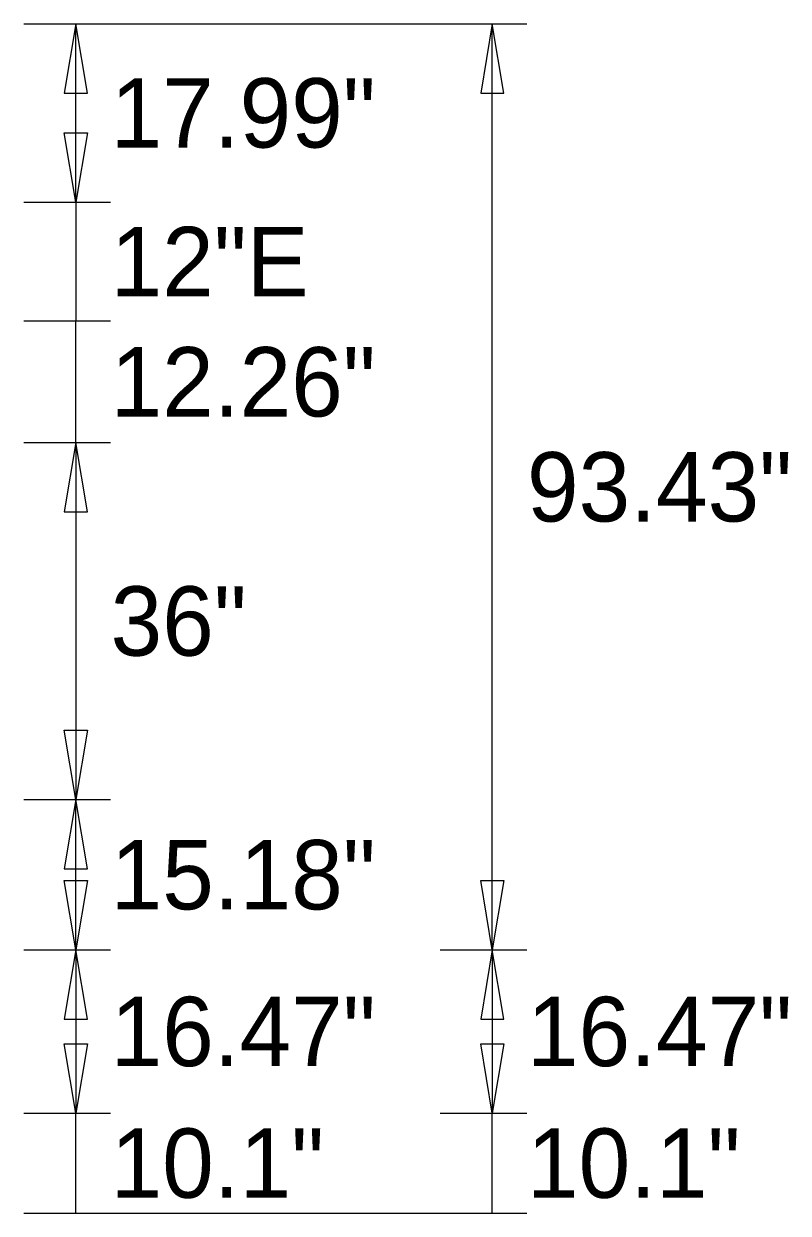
# Model space of a CAD drawing. Extents: x 2149934 to 2150188, y 145113 to 145238.
# Drawn here: x 2149967.33 to 2149973.75, y 145137.95 to 145147.95 of the extents above; entities that cross this region are included whole.
import ezdxf

# ---------------------------------------------------------------- set-up
doc = ezdxf.new("R2010")
doc.units = 0
doc.layers.add('GSDIMS', color=7, linetype='Continuous')

msp = doc.modelspace()

# ---------------------------------------------------------------- linework, layer by layer
at = {"layer": 'GSDIMS'}
for p, q in [((2149967.326, 145147.954), (2149968.055, 145147.954)), ((2149967.326, 145147.954), (2149970.826, 145147.954)), ((2149967.763, 145146.455), (2149967.763, 145147.954)), ((2149970.826, 145147.954), (2149971.555, 145147.954)), ((2149971.263, 145140.168), (2149971.263, 145147.954)), ((2149967.326, 145146.455), (2149968.055, 145146.455)), ((2149967.326, 145146.455), (2149968.055, 145146.455)), ((2149967.763, 145146.455), (2149967.763, 145145.455)), ((2149967.326, 145145.455), (2149968.055, 145145.455)), ((2149967.326, 145145.455), (2149968.055, 145145.455)), ((2149967.763, 145144.433), (2149967.763, 145145.455)), ((2149967.326, 145144.433), (2149968.055, 145144.433)), ((2149967.326, 145144.433), (2149968.055, 145144.433)), ((2149967.763, 145144.433), (2149967.763, 145141.433)), ((2149967.326, 145141.433), (2149968.055, 145141.433)), ((2149967.326, 145141.433), (2149968.055, 145141.433)), ((2149967.763, 145140.168), (2149967.763, 145141.433)), ((2149967.326, 145140.168), (2149968.055, 145140.168)), ((2149967.326, 145140.168), (2149968.055, 145140.168)), ((2149967.763, 145140.168), (2149967.763, 145138.795)), ((2149970.826, 145140.168), (2149971.555, 145140.168)), ((2149970.826, 145140.168), (2149971.555, 145140.168)), ((2149971.263, 145140.168), (2149971.263, 145138.795)), ((2149967.326, 145138.795), (2149968.055, 145138.795)), ((2149967.326, 145138.795), (2149968.055, 145138.795)), ((2149967.763, 145137.954), (2149967.763, 145138.795)), ((2149970.826, 145138.795), (2149971.555, 145138.795)), ((2149970.826, 145138.795), (2149971.555, 145138.795)), ((2149971.263, 145137.954), (2149971.263, 145138.795)), ((2149967.326, 145137.954), (2149968.055, 145137.954)), ((2149967.326, 145137.954), (2149970.826, 145137.954)), ((2149970.826, 145137.954), (2149971.555, 145137.954))]:
    msp.add_line(p, q, dxfattribs=at)
for points in [[(2149967.763, 145147.954), (2149967.666, 145147.37), (2149967.86, 145147.37)], [(2149971.263, 145147.954), (2149971.166, 145147.37), (2149971.36, 145147.37)], [(2149967.763, 145146.455), (2149967.666, 145147.038), (2149967.86, 145147.038)], [(2149967.763, 145144.433), (2149967.666, 145143.85), (2149967.86, 145143.85)], [(2149967.763, 145141.433), (2149967.666, 145142.016), (2149967.86, 145142.016)], [(2149967.763, 145141.433), (2149967.666, 145140.849), (2149967.86, 145140.849)], [(2149967.763, 145140.168), (2149967.666, 145140.751), (2149967.86, 145140.751)], [(2149971.263, 145140.168), (2149971.166, 145140.751), (2149971.36, 145140.751)], [(2149967.763, 145140.168), (2149967.666, 145139.584), (2149967.86, 145139.584)], [(2149971.263, 145140.168), (2149971.166, 145139.584), (2149971.36, 145139.584)], [(2149967.763, 145138.795), (2149967.666, 145139.379), (2149967.86, 145139.379)], [(2149971.263, 145138.795), (2149971.166, 145139.379), (2149971.36, 145139.379)]]:
    msp.add_lwpolyline(points, close=True, dxfattribs=at)

# ---------------------------------------------------------------- texts
for s, p in [('17.99"', (2149968.055, 145146.913)), ('12"E', (2149968.055, 145145.663)), ('12.26"', (2149968.055, 145144.652)), ('93.43"', (2149971.555, 145143.769)), ('36"', (2149968.055, 145142.641)), ('15.18"', (2149968.055, 145140.508)), ('16.47"', (2149968.055, 145139.19)), ('16.47"', (2149971.555, 145139.19)), ('10.1"', (2149968.055, 145138.083)), ('10.1"', (2149971.555, 145138.083))]:
    msp.add_text(s, height=0.5833, dxfattribs=at).set_placement(p)

doc.saveas('drawing.dxf')
